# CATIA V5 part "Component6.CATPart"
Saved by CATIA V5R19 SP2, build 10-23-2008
Part number: Component6
Definition: Component6
Nomenclature: Component6
Source: Unknown
Bounding box of the stored display mesh (mm): x -4.283 to 0.4, y 0 to 2.367, z 0 to 3.3
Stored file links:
  Z:\fausse table rondelle-20220905T211342Z-001\fausse table rondelle\Component6.CATPart
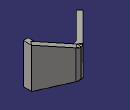
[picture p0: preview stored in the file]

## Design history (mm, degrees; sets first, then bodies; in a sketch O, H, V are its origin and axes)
AxisSystem1: origin (0, 0, 0), X (1, 0, 0), Y (0, 1, 0), Z (0, 0, 1)
Body1 "Body1" (main body)
  Solid1: solid without history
